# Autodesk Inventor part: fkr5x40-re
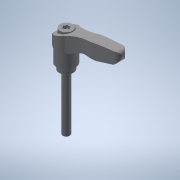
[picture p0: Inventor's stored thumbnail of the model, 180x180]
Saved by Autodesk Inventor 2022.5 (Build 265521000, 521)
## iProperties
Created: 2016-12
Part Number: fkr5x40-re
Material: 一般
Document SubType Name: Modeling
Designer: imaocorp
Density: 1 g/cm^3
Appearance: 既定
Author: imaocorp
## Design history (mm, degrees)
node "fkr5x40-re.x_t1"
node "K1000_105040_012"
node "Base1"
